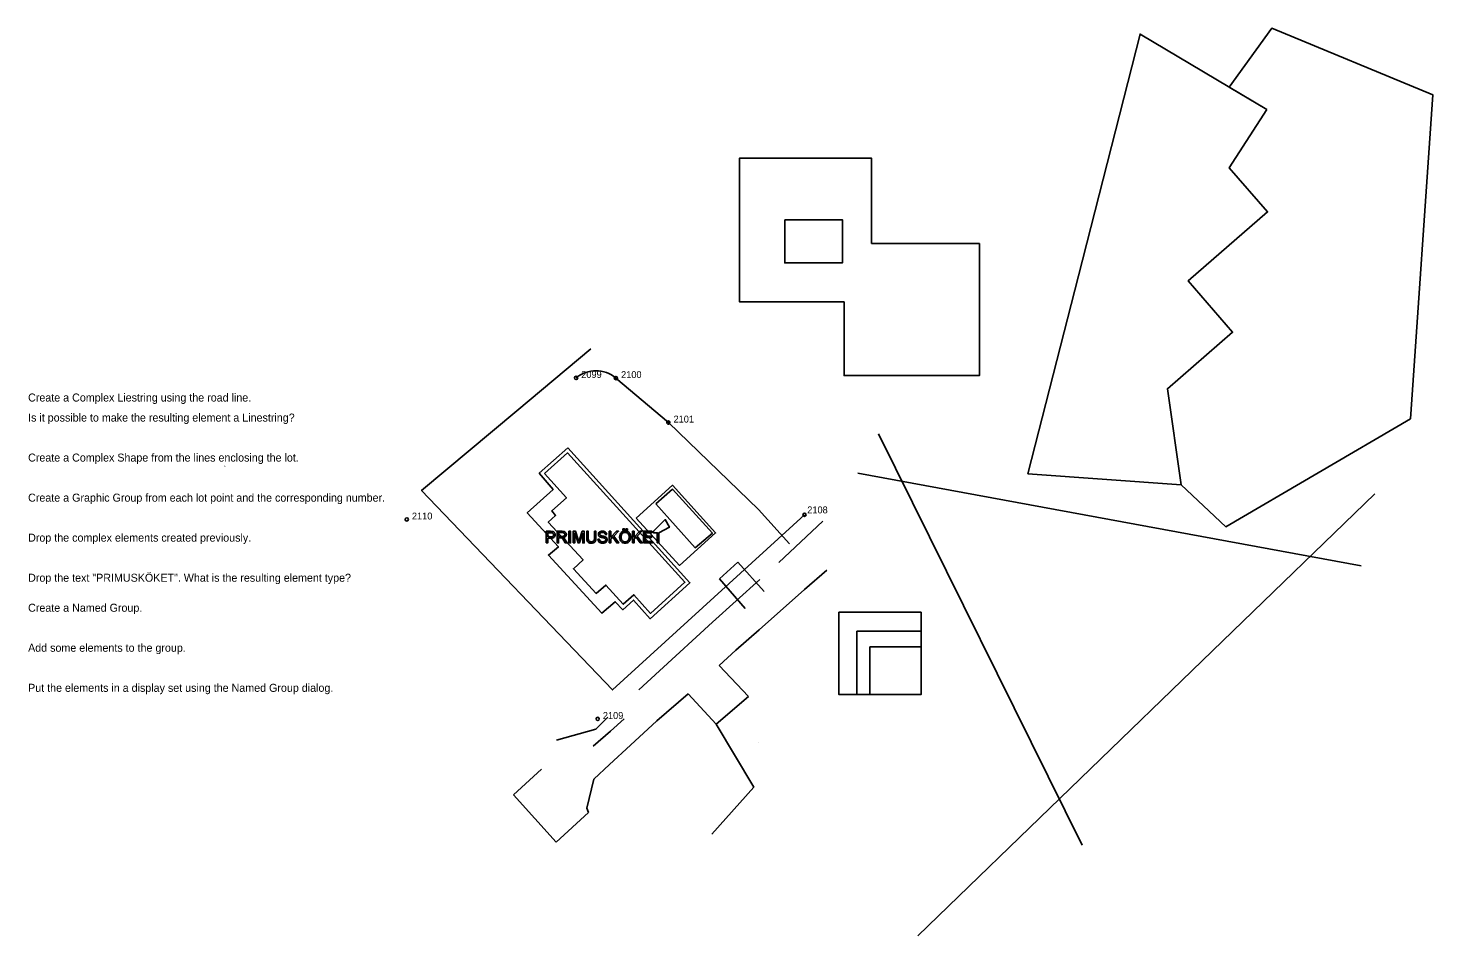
# Model space of a CAD drawing. Extents: x 1517812 to 1518016, y 6495442 to 6495573.
import ezdxf

# ---------------------------------------------------------------- set-up
doc = ezdxf.new("R2010")
doc.units = 0
doc.layers.add('Default', color=7, linetype='Continuous')
doc.layers.add('Instruktioner', color=7, linetype='Continuous')

msp = doc.modelspace()

# ---------------------------------------------------------------- linework, layer by layer
at = {"layer": 'Default'}
for p, q in [((1517986.19, 6495564.83), (1517991.66, 6495561.58)), ((1517964.84, 6495454.74), (1517935.23, 6495514.47)), ((1517885.93, 6495508.77), (1517890.11, 6495512.46)), ((1517932.24, 6495508.74), (1518005.39, 6495495.3)), ((1518007.38, 6495505.76), (1517940.95, 6495441.55)), ((1517927.16, 6495501.81), (1517920.79, 6495495.76)), ((1517914.82, 6495495.84), (1517912.13, 6495493.39)), ((1517918.63, 6495491.55), (1517914.82, 6495495.84)), ((1517924.5, 6495491.87), (1517927.76, 6495494.69)), ((1517918.02, 6495493.31), (1517911.13, 6495487.12)), ((1517912.13, 6495493.39), (1517915.87, 6495489.1)), ((1517917.92, 6495486), (1517924.5, 6495491.87)), ((1517911.13, 6495487.12), (1517903.45, 6495480.07)), ((1517914.53, 6495483.07), (1517917.92, 6495486)), ((1517912.08, 6495480.84), (1517914.53, 6495483.07)), ((1517903.45, 6495480.07), (1517900.44, 6495477.3)), ((1517916.34, 6495476.31), (1517912.08, 6495480.84)), ((1517903.07, 6495472.81), (1517907.62, 6495476.73)), ((1517907.62, 6495476.73), (1517911.65, 6495472.32)), ((1517911.65, 6495472.32), (1517916.34, 6495476.31)), ((1517894.19, 6495471.58), (1517888.47, 6495469.98)), ((1517895.94, 6495473.3), (1517894.19, 6495471.58)), ((1517898.28, 6495473.1), (1517896.31, 6495471.28)), ((1517899.2, 6495469.23), (1517903.07, 6495472.81)), ((1517911.65, 6495472.32), (1517917.13, 6495463.16)), ((1517896.31, 6495471.28), (1517893.78, 6495469.1)), ((1517917.82, 6495469.57), (1517917.82, 6495469.58)), ((1517896.18, 6495466.46), (1517899.2, 6495469.23)), ((1517886.31, 6495465.78), (1517882.23, 6495462.04)), ((1517893.89, 6495464.3), (1517896.18, 6495466.46)), ((1517892.89, 6495460.09), (1517893.89, 6495464.3)), ((1517882.23, 6495462.04), (1517888.42, 6495455.17)), ((1517917.13, 6495463.16), (1517911.03, 6495456.33)), ((1517888.42, 6495455.17), (1517893.12, 6495459.46)), ((1517893.12, 6495459.46), (1517892.89, 6495460.09))]:
    msp.add_line(p, q, dxfattribs=at)
for points in [[(1517979.22, 6495507.08), (1517985.69, 6495500.98), (1518012.56, 6495516.66), (1518015.8, 6495563.69), (1517992.41, 6495573.4), (1517986.19, 6495564.83)], [(1517991.66, 6495561.58), (1517986.2, 6495553.12), (1517991.77, 6495546.71), (1517980.22, 6495536.67), (1517986.69, 6495529.23), (1517977.23, 6495521.01), (1517979.22, 6495507.08)], [(1517934.23, 6495542.09), (1517934.23, 6495554.53), (1517915.08, 6495554.53), (1517915.08, 6495533.63), (1517930.25, 6495533.63)], [(1517934.23, 6495542.09), (1517934.23, 6495554.53), (1517915.08, 6495554.53), (1517915.08, 6495533.63), (1517930.25, 6495533.63)], [(1517921.63, 6495545.56), (1517930, 6495545.56), (1517930, 6495539.3), (1517921.63, 6495539.3), (1517921.63, 6495545.56)], [(1517930.25, 6495533.63), (1517930.25, 6495522.93), (1517949.91, 6495522.93), (1517949.91, 6495542.09), (1517934.23, 6495542.09)], [(1517930.25, 6495533.63), (1517930.25, 6495522.93), (1517949.91, 6495522.93), (1517949.91, 6495542.09), (1517934.23, 6495542.09)], [(1517893.46, 6495526.8), (1517882.69, 6495517.8), (1517868.86, 6495506.24), (1517896.61, 6495477.27), (1517924.5, 6495502.71)], [(1517922.34, 6495498.5), (1517917.81, 6495503.47), (1517904.72, 6495516.11), (1517897.1, 6495522.57)], [(1517890.11, 6495512.46), (1517907.85, 6495492.85), (1517902.07, 6495487.62), (1517899.64, 6495490.33), (1517898.1, 6495488.93), (1517897.01, 6495490.08), (1517895.07, 6495488.4), (1517887.3, 6495496.86), (1517888.75, 6495498.05), (1517884.23, 6495502.99), (1517887.98, 6495506.39), (1517885.93, 6495508.77)], [(1517886.74, 6495508.7), (1517890.09, 6495511.7), (1517907.13, 6495492.92), (1517902.14, 6495488.38), (1517899.71, 6495491.09), (1517898.16, 6495489.73), (1517895.64, 6495492.51), (1517894.25, 6495491.29), (1517890.92, 6495494.88), (1517892.33, 6495496.17), (1517887.27, 6495501.64), (1517888.33, 6495502.62), (1517887.78, 6495503.27), (1517889.92, 6495505.18), (1517886.74, 6495508.7)], [(1517900.06, 6495502.24), (1517905.34, 6495507.01), (1517911.59, 6495500.09), (1517906.34, 6495495.36), (1517900.05, 6495502.22)], [(1517902.91, 6495504.29), (1517905.3, 6495506.43), (1517911.11, 6495500.06), (1517908.6, 6495497.93), (1517902.91, 6495504.29)], [(1517903.11, 6495498.63), (1517903.11, 6495500.11), (1517902.56, 6495500.11), (1517902.56, 6495500.31), (1517904.27, 6495502.02), (1517904.87, 6495500.9), (1517903.34, 6495500.11), (1517903.34, 6495498.63), (1517903.11, 6495498.63)], [(1517886.97, 6495498.63), (1517886.97, 6495500.31), (1517887.61, 6495500.31)], [(1517887.63, 6495500.11), (1517887.2, 6495500.11), (1517887.2, 6495499.51)], [(1517888.55, 6495498.63), (1517888.55, 6495500.31), (1517889.29, 6495500.31)], [(1517889.3, 6495500.13), (1517888.77, 6495500.13), (1517888.77, 6495499.57)], [(1517890.28, 6495498.63), (1517890.28, 6495500.31), (1517890.51, 6495500.31), (1517890.51, 6495498.63), (1517890.28, 6495498.63)], [(1517890.89, 6495498.63), (1517890.89, 6495500.31), (1517891.23, 6495500.31), (1517891.63, 6495499.12)], [(1517891.8, 6495499.14), (1517892.2, 6495500.31), (1517892.5, 6495500.31), (1517892.5, 6495498.63), (1517892.29, 6495498.63), (1517892.29, 6495500.04), (1517891.8, 6495498.63), (1517891.6, 6495498.63), (1517891.11, 6495500.06), (1517891.11, 6495498.63), (1517890.89, 6495498.63)], [(1517892.87, 6495499.34), (1517892.87, 6495500.31), (1517893.09, 6495500.31), (1517893.09, 6495499.34)], [(1517893.97, 6495500.31), (1517894.19, 6495500.31), (1517894.19, 6495499.34)], [(1517893.97, 6495499.34), (1517893.97, 6495500.31)], [(1517896.13, 6495498.63), (1517896.13, 6495500.31), (1517896.35, 6495500.31), (1517896.35, 6495499.48), (1517897.19, 6495500.31), (1517897.49, 6495500.31), (1517896.78, 6495499.63), (1517897.52, 6495498.63), (1517897.23, 6495498.63), (1517896.63, 6495499.48), (1517896.35, 6495499.21), (1517896.35, 6495498.63), (1517896.13, 6495498.63)], [(1517898.13, 6495500.42), (1517898.13, 6495500.65), (1517898.35, 6495500.65), (1517898.35, 6495500.42), (1517898.13, 6495500.42)], [(1517898.56, 6495500.42), (1517898.56, 6495500.65), (1517898.78, 6495500.65), (1517898.78, 6495500.42), (1517898.56, 6495500.42)], [(1517899.53, 6495498.63), (1517899.53, 6495500.31), (1517899.75, 6495500.31), (1517899.75, 6495499.48), (1517900.59, 6495500.31), (1517900.89, 6495500.31), (1517900.19, 6495499.63), (1517900.92, 6495498.63), (1517900.63, 6495498.63), (1517900.03, 6495499.48), (1517899.75, 6495499.21), (1517899.75, 6495498.63), (1517899.53, 6495498.63)], [(1517901.12, 6495498.63), (1517901.12, 6495500.31), (1517902.34, 6495500.31), (1517902.34, 6495500.11), (1517901.34, 6495500.11), (1517901.34, 6495499.6), (1517902.27, 6495499.6), (1517902.27, 6495499.4), (1517901.34, 6495499.4), (1517901.34, 6495498.82), (1517902.38, 6495498.82), (1517902.38, 6495498.63), (1517901.12, 6495498.63)], [(1517887.63, 6495499.31), (1517887.2, 6495499.31), (1517887.2, 6495498.63), (1517886.97, 6495498.63)], [(1517887.2, 6495499.51), (1517887.63, 6495499.51)], [(1517889.03, 6495499.38), (1517888.77, 6495499.38), (1517888.77, 6495498.63), (1517888.55, 6495498.63)], [(1517888.77, 6495499.57), (1517889.25, 6495499.57)], [(1517889.74, 6495499.08), (1517890.03, 6495498.63), (1517889.75, 6495498.63), (1517889.53, 6495498.98)], [(1517894.49, 6495499.17), (1517894.7, 6495499.19)], [(1517895.78, 6495499.84), (1517895.57, 6495499.82)]]:
    msp.add_lwpolyline(points, dxfattribs=at)
for points in [[(1517991.66, 6495561.58), (1517973.25, 6495572.53), (1517964.29, 6495537.44), (1517956.95, 6495508.67), (1517979.22, 6495507.08), (1517977.23, 6495521.01), (1517986.69, 6495529.23), (1517980.22, 6495536.67), (1517991.77, 6495546.71), (1517986.2, 6495553.12)], [(1517921.63, 6495545.56), (1517930, 6495545.56), (1517930, 6495539.3), (1517921.63, 6495539.3)], [(1517929.5, 6495488.55), (1517941.44, 6495488.55), (1517941.44, 6495476.61), (1517929.5, 6495476.61)], [(1517932.1, 6495485.79), (1517941.44, 6495485.79), (1517941.44, 6495476.61), (1517932.1, 6495476.61)], [(1517933.97, 6495483.52), (1517941.44, 6495483.52), (1517941.44, 6495476.61), (1517933.97, 6495476.61)]]:
    msp.add_lwpolyline(points, close=True, dxfattribs=at)
for centre in [(1517891.31, 6495522.59), (1517897.1, 6495522.57), (1517904.72, 6495516.11), (1517866.71, 6495502.03), (1517924.5, 6495502.71), (1517894.45, 6495473.06)]:
    msp.add_circle(centre, 0.237, dxfattribs=at)
for centre, radius, start, end in [((1517894.19, 6495519.13), 4.5, 49.6994, 129.8503), ((1517840.26, 6495509.75), 0.000018, 278.2325, 316.1166), ((1517917.12, 6495463.16), 0.001, 318.2443, 30.8561)]:
    msp.add_arc(centre, radius, start, end, dxfattribs=at)
for points in [[(1517887.61, 6495500.31), (1517887.78, 6495500.31), (1517887.86, 6495500.3), (1517887.99, 6495500.28), (1517888.07, 6495500.22), (1517888.16, 6495500.16), (1517888.21, 6495500.05), (1517888.26, 6495499.95), (1517888.26, 6495499.82), (1517888.26, 6495499.61), (1517888.12, 6495499.46), (1517887.99, 6495499.31), (1517887.63, 6495499.31)], [(1517887.63, 6495499.51), (1517887.85, 6495499.51), (1517887.94, 6495499.59), (1517888.03, 6495499.67), (1517888.03, 6495499.82), (1517888.03, 6495499.92), (1517887.98, 6495500), (1517887.92, 6495500.07), (1517887.83, 6495500.1), (1517887.78, 6495500.11), (1517887.63, 6495500.11)], [(1517889.25, 6495499.57), (1517889.4, 6495499.57), (1517889.49, 6495499.6), (1517889.58, 6495499.63), (1517889.62, 6495499.7), (1517889.67, 6495499.77), (1517889.67, 6495499.85), (1517889.67, 6495499.97), (1517889.58, 6495500.05), (1517889.49, 6495500.13), (1517889.3, 6495500.13)], [(1517889.29, 6495500.31), (1517889.52, 6495500.31), (1517889.64, 6495500.27), (1517889.75, 6495500.22), (1517889.83, 6495500.11), (1517889.9, 6495499.99), (1517889.9, 6495499.85), (1517889.9, 6495499.67), (1517889.78, 6495499.55), (1517889.66, 6495499.43), (1517889.42, 6495499.39), (1517889.51, 6495499.35), (1517889.55, 6495499.31), (1517889.65, 6495499.22), (1517889.74, 6495499.08)], [(1517895.57, 6495499.82), (1517895.55, 6495499.98), (1517895.45, 6495500.06), (1517895.35, 6495500.14), (1517895.15, 6495500.14), (1517894.95, 6495500.14), (1517894.86, 6495500.07), (1517894.76, 6495500), (1517894.76, 6495499.89), (1517894.76, 6495499.8), (1517894.83, 6495499.74), (1517894.9, 6495499.68), (1517895.17, 6495499.62), (1517895.44, 6495499.56), (1517895.54, 6495499.51), (1517895.69, 6495499.45), (1517895.76, 6495499.34), (1517895.83, 6495499.24), (1517895.83, 6495499.1), (1517895.83, 6495498.97), (1517895.75, 6495498.85), (1517895.68, 6495498.73), (1517895.53, 6495498.66), (1517895.39, 6495498.6), (1517895.21, 6495498.6), (1517894.98, 6495498.6), (1517894.82, 6495498.66), (1517894.67, 6495498.73), (1517894.58, 6495498.86), (1517894.49, 6495499), (1517894.49, 6495499.17)], [(1517894.7, 6495499.19), (1517894.71, 6495499.06), (1517894.77, 6495498.98), (1517894.82, 6495498.9), (1517894.94, 6495498.85), (1517895.05, 6495498.8), (1517895.2, 6495498.8), (1517895.32, 6495498.8), (1517895.42, 6495498.83), (1517895.52, 6495498.87), (1517895.57, 6495498.94), (1517895.62, 6495499.01), (1517895.62, 6495499.08), (1517895.62, 6495499.16), (1517895.57, 6495499.22), (1517895.52, 6495499.28), (1517895.42, 6495499.32), (1517895.35, 6495499.35), (1517895.12, 6495499.4), (1517894.88, 6495499.46), (1517894.79, 6495499.51), (1517894.67, 6495499.57), (1517894.61, 6495499.67), (1517894.55, 6495499.76), (1517894.55, 6495499.88), (1517894.55, 6495500), (1517894.62, 6495500.12), (1517894.7, 6495500.23), (1517894.83, 6495500.28), (1517894.97, 6495500.34), (1517895.14, 6495500.34), (1517895.33, 6495500.34), (1517895.48, 6495500.28), (1517895.62, 6495500.22), (1517895.7, 6495500.1), (1517895.77, 6495499.99), (1517895.78, 6495499.84)], [(1517897.64, 6495499.45), (1517897.64, 6495499.87), (1517897.86, 6495500.1), (1517898.09, 6495500.34), (1517898.45, 6495500.34), (1517898.68, 6495500.34), (1517898.87, 6495500.23), (1517899.06, 6495500.12), (1517899.15, 6495499.92), (1517899.25, 6495499.72), (1517899.25, 6495499.47), (1517899.25, 6495499.21), (1517899.15, 6495499.01), (1517899.05, 6495498.81), (1517898.86, 6495498.7), (1517898.67, 6495498.6), (1517898.45, 6495498.6), (1517898.21, 6495498.6), (1517898.02, 6495498.71), (1517897.83, 6495498.83), (1517897.74, 6495499.03), (1517897.64, 6495499.23), (1517897.64, 6495499.45)], [(1517897.87, 6495499.44), (1517897.87, 6495499.14), (1517898.03, 6495498.96), (1517898.2, 6495498.79), (1517898.44, 6495498.79), (1517898.7, 6495498.79), (1517898.86, 6495498.97), (1517899.02, 6495499.14), (1517899.02, 6495499.47), (1517899.02, 6495499.67), (1517898.95, 6495499.83), (1517898.88, 6495499.98), (1517898.75, 6495500.07), (1517898.61, 6495500.15), (1517898.45, 6495500.15), (1517898.21, 6495500.15), (1517898.04, 6495499.99), (1517897.87, 6495499.82), (1517897.87, 6495499.44)], [(1517889.53, 6495498.98), (1517889.43, 6495499.13), (1517889.37, 6495499.21), (1517889.31, 6495499.29), (1517889.26, 6495499.32), (1517889.21, 6495499.35), (1517889.15, 6495499.37), (1517889.12, 6495499.38), (1517889.03, 6495499.38)], [(1517891.63, 6495499.12), (1517891.68, 6495498.95), (1517891.71, 6495498.87), (1517891.74, 6495498.96), (1517891.8, 6495499.14)], [(1517894.19, 6495499.34), (1517894.19, 6495499.08), (1517894.13, 6495498.93), (1517894.08, 6495498.78), (1517893.93, 6495498.69), (1517893.78, 6495498.6), (1517893.53, 6495498.6), (1517893.3, 6495498.6), (1517893.14, 6495498.68), (1517892.99, 6495498.76), (1517892.93, 6495498.92), (1517892.87, 6495499.07), (1517892.87, 6495499.34)], [(1517893.09, 6495499.34), (1517893.09, 6495499.12), (1517893.13, 6495499.02), (1517893.17, 6495498.91), (1517893.27, 6495498.86), (1517893.37, 6495498.8), (1517893.51, 6495498.8), (1517893.76, 6495498.8), (1517893.86, 6495498.91), (1517893.97, 6495499.02), (1517893.97, 6495499.34)]]:
    msp.add_open_spline(points, degree=3, dxfattribs=at)

# ---------------------------------------------------------------- texts
for s, p in [('2099', (1517892.06, 6495522.59)), ('2100', (1517897.85, 6495522.57)), ('2101', (1517905.47, 6495516.11)), ('2110', (1517867.46, 6495502.03)), ('2108', (1517924.9, 6495502.92)), ('2109', (1517895.2, 6495473.06))]:
    msp.add_text(s, height=1, dxfattribs=at).set_placement(p)
at = {"layer": 'Instruktioner'}
for s, p in [('Create a Complex Liestring using the road line.', (1517811.7, 6495519.16)), ('Is it possible to make the resulting element a Linestring?', (1517811.7, 6495516.25)), ('Create a Complex Shape from the lines enclosing the lot.', (1517811.7, 6495510.44)), ('Create a Graphic Group from each lot point and the corresponding number. ', (1517811.7, 6495504.62)), ('Drop the complex elements created previously.', (1517811.7, 6495498.81)), ('Drop the text "PRIMUSKÖKET". What is the resulting element type?', (1517811.7, 6495492.99)), ('Create a Named Group.', (1517811.7, 6495488.63)), ('Add some elements to the group.', (1517811.7, 6495482.82)), ('Put the elements in a display set using the Named Group dialog.', (1517811.7, 6495477))]:
    msp.add_text(s, height=1.1629, dxfattribs=at).set_placement(p)

doc.saveas('drawing.dxf')
